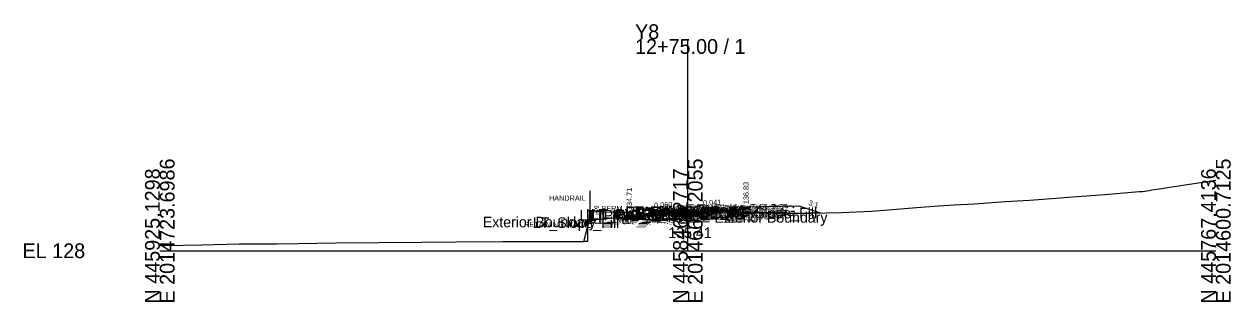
# Model space of a CAD drawing. Extents: x -26 to 1403, y -10 to 8043.
# Drawn here: x -25.7 to 202.8, y 5490.3 to 5543 of the extents above; entities that cross this region are included whole.
import ezdxf

# ---------------------------------------------------------------- set-up
doc = ezdxf.new("R2010")
doc.units = 0
for name, color, linetype in [('Default', 7, 'Continuous'), ('Exist CMT Pavement', 7, 'Continuous'), ('Exist Cross Section Cell', 7, 'Continuous'), ('Exist XS Center Line Elevation Label', 7, 'Continuous'), ('Exist XS Ground Line', 7, 'Continuous'), ('Prop CMT Conc Surface', 7, 'Continuous'), ('Prop CMT Concrete Structures', 7, 'Continuous'), ('Prop CMT Pvmt Course 1', 7, 'Continuous'), ('Prop CMT Pvmt Course 1 CG', 7, 'Continuous'), ('Prop CMT Pvmt Course 1 Wedge', 7, 'Continuous'), ('Prop CMT Pvmt Course 2', 7, 'Continuous'), ('Prop CMT Pvmt Course 2 Wedge', 7, 'Continuous'), ('Prop CMT Pvmt Course 3', 7, 'Continuous'), ('Prop CMT Pvmt Course 3 Wedge', 7, 'Continuous'), ('Prop CMT Pvmt Surface', 7, 'Continuous'), ('Prop CMT Pvmt Wedge Surface 1', 7, 'Continuous'), ('Prop CMT Pvmt Wedge Surface 2', 7, 'Continuous'), ('Prop CMT Pvmt Wedge Surface 3', 7, 'Continuous'), ('Prop CMT Slope Grass', 7, 'Continuous'), ('Prop CMT Subgrade Earthwork', 7, 'Continuous'), ('Prop XS Earthwork Shape', 7, 'Continuous'), ('Prop XS Hydro Elevations', 7, 'Continuous'), ('Prop XS Retaining Wall', 7, 'Continuous'), ('Prop XS SE Text', 7, 'Continuous'), ('Prop XS Side Slope Text', 7, 'Continuous'), ('Prop XS Vertical Lines', 7, 'Continuous'), ('Prop XS Wedging', 7, 'Continuous'), ('Scratch_Level_0', 7, 'Continuous')]:
    doc.layers.add(name, color=color, linetype=linetype)

msp = doc.modelspace()

# ---------------------------------------------------------------- linework, layer by layer
at = {"layer": 'Exist CMT Pavement'}
msp.add_lwpolyline([(91.92, 5506.74), (100.14, 5507.42), (107.98, 5507.57)], dxfattribs=at)
at = {"layer": 'Exist Cross Section Cell'}
for p, q in [((100, 5500), (100, 5540.12)), ((0, 5500), (100, 5500)), ((100, 5500), (200, 5500))]:
    msp.add_line(p, q, dxfattribs=at)
at = {"layer": 'Exist XS Ground Line'}
msp.add_lwpolyline([(0, 5501.01), (0.81, 5501.02), (7.95, 5501.11), (15.06, 5501.32), (20.63, 5501.3), (22.18, 5501.31), (26.19, 5501.38), (33.31, 5501.53), (49.55, 5501.63), (56.04, 5501.69), (64.94, 5501.74), (68.16, 5501.77), (75.26, 5501.75), (79.61, 5501.76), (80.32, 5501.76), (80.7, 5503.19), (81.37, 5505.83), (82.14, 5505.89), (85.97, 5506.23), (88.19, 5506.43), (89.76, 5506.56), (90.69, 5506.63), (100.14, 5507.42), (108.04, 5507.57), (108.43, 5507.54), (108.86, 5507.5), (109.95, 5507.38), (110.41, 5507.34), (112.61, 5507.23), (113.06, 5507.22), (113.53, 5507.21), (114.01, 5507.21), (114.64, 5507.21), (115.24, 5507.19), (116.01, 5507.18), (116.76, 5507.17), (117.48, 5507.16), (118.17, 5507.16), (118.81, 5507.15), (119.41, 5507.15), (120.44, 5507.09), (129.07, 5507.23), (134.77, 5507.51), (138.02, 5507.73), (143.32, 5508.18), (147.46, 5508.51), (150.45, 5508.69), (154.28, 5508.92), (160.14, 5509.31), (164.7, 5509.6), (170.55, 5510.02), (172.82, 5510.21), (178.95, 5510.69), (185.5, 5511.21), (186.08, 5511.25), (187.34, 5511.4), (187.89, 5511.52), (188.84, 5511.68), (200, 5513.37)], dxfattribs=at)
at = {"layer": 'Prop CMT Conc Surface'}
for points in [[(109.03, 5507.83), (111.03, 5507.83)], [(111.03, 5507.83), (111.03, 5508.33), (111.53, 5508.33)], [(88.91, 5506.71), (88.91, 5507.21), (88.41, 5507.21)], [(90.91, 5506.91), (88.91, 5506.71)]]:
    msp.add_lwpolyline(points, dxfattribs=at)
at = {"layer": 'Prop CMT Concrete Structures'}
for points in [[(109.03, 5507.83), (111.03, 5507.83), (111.03, 5508.33), (111.53, 5508.33)], [(111.53, 5508.33), (111.53, 5507.35), (109.03, 5507.24)], [(109.03, 5507.24), (109.03, 5507.83)], [(90.91, 5506.91), (88.91, 5506.71), (88.91, 5507.21), (88.41, 5507.21)], [(88.41, 5507.21), (88.41, 5506.18), (90.91, 5506.33)], [(90.91, 5506.33), (90.91, 5506.91)]]:
    msp.add_lwpolyline(points, dxfattribs=at)
at = {"layer": 'Prop CMT Pvmt Course 1'}
for points in [[(100, 5507.46), (109.03, 5507.83)], [(107.98, 5507.66), (100, 5507.33)], [(107.98, 5507.53), (107.98, 5507.66)], [(109.03, 5507.83), (109.03, 5507.58)], [(109.03, 5507.83), (109.03, 5507.58)], [(100, 5507.46), (90.91, 5506.91)], [(90.91, 5506.91), (90.91, 5506.66)], [(90.91, 5506.91), (90.91, 5506.66)], [(90.91, 5506.66), (91.92, 5506.72)], [(91.92, 5506.85), (100, 5507.33)], [(91.92, 5506.72), (91.92, 5506.85)], [(100, 5507.21), (100, 5507.46)], [(100, 5507.21), (100, 5507.46)], [(100, 5507.33), (100, 5507.21), (100, 5507.21)], [(100, 5507.33), (100, 5507.21), (100, 5507.21)], [(109.03, 5507.58), (107.98, 5507.53)]]:
    msp.add_lwpolyline(points, dxfattribs=at)
at = {"layer": 'Prop CMT Pvmt Course 1 CG'}
for points in [[(90.91, 5506.33), (87.91, 5506.15), (87.6, 5505.84)], [(87.6, 5505.84), (90.91, 5506.04)], [(90.91, 5506.04), (90.91, 5506.33)], [(109.03, 5507.24), (112.03, 5507.37), (112.31, 5507.09)], [(109.03, 5506.95), (109.03, 5507.24)], [(112.31, 5507.09), (109.03, 5506.95)]]:
    msp.add_lwpolyline(points, dxfattribs=at)
at = {"layer": 'Prop CMT Pvmt Course 1 Wedge'}
for points in [[(100, 5507.33), (107.98, 5507.66)], [(100, 5507.33), (91.92, 5506.85)]]:
    msp.add_lwpolyline(points, dxfattribs=at)
at = {"layer": 'Prop CMT Pvmt Course 2'}
for points in [[(91.92, 5506.72), (90.91, 5506.66)], [(90.91, 5506.66), (90.91, 5506.41)], [(90.91, 5506.66), (90.91, 5506.41)], [(90.91, 5506.41), (91.92, 5506.47)], [(91.92, 5506.47), (91.92, 5506.72)], [(107.98, 5507.53), (109.03, 5507.58)], [(107.98, 5507.28), (107.98, 5507.53)], [(109.03, 5507.33), (107.98, 5507.28)], [(109.03, 5507.58), (109.03, 5507.33)], [(109.03, 5507.58), (109.03, 5507.33)]]:
    msp.add_lwpolyline(points, dxfattribs=at)
at = {"layer": 'Prop CMT Pvmt Course 2 Wedge'}
for points in [[(100, 5507.21), (91.92, 5506.72)], [(100, 5507.21), (107.98, 5507.53)]]:
    msp.add_lwpolyline(points, dxfattribs=at)
at = {"layer": 'Prop CMT Pvmt Course 3'}
for points in [[(91.92, 5506.47), (90.91, 5506.41)], [(90.91, 5506.41), (90.91, 5506.04)], [(90.91, 5506.41), (90.91, 5506.04)], [(90.91, 5506.04), (91.92, 5506.1)], [(91.92, 5506.1), (91.92, 5506.47)], [(107.98, 5507.28), (109.03, 5507.33)], [(107.98, 5506.91), (107.98, 5507.28)], [(109.03, 5506.95), (107.98, 5506.91)], [(109.03, 5507.33), (109.03, 5506.95)], [(109.03, 5507.33), (109.03, 5506.95)]]:
    msp.add_lwpolyline(points, dxfattribs=at)
at = {"layer": 'Prop CMT Pvmt Course 3 Wedge'}
for points in [[(100, 5506.96), (91.92, 5506.47)], [(100, 5506.96), (107.98, 5507.28)]]:
    msp.add_lwpolyline(points, dxfattribs=at)
at = {"layer": 'Prop CMT Pvmt Surface'}
for points in [[(100, 5507.46), (109.03, 5507.83)], [(100, 5507.46), (90.91, 5506.91)]]:
    msp.add_lwpolyline(points, dxfattribs=at)
at = {"layer": 'Prop CMT Pvmt Wedge Surface 1'}
for points in [[(100, 5507.33), (107.98, 5507.66)], [(107.98, 5507.66), (107.98, 5507.53)], [(109.03, 5507.58), (109.03, 5507.83)], [(90.91, 5506.66), (90.91, 5506.91)], [(90.91, 5506.66), (90.91, 5506.91)], [(91.92, 5506.72), (90.91, 5506.66)], [(100, 5507.33), (91.92, 5506.85)], [(91.92, 5506.85), (91.92, 5506.72)], [(107.98, 5507.53), (109.03, 5507.58)]]:
    msp.add_lwpolyline(points, dxfattribs=at)
at = {"layer": 'Prop CMT Pvmt Wedge Surface 2'}
for points in [[(109.03, 5507.58), (109.03, 5507.83)], [(100, 5507.21), (90.91, 5506.66)], [(90.91, 5506.66), (90.91, 5506.91)], [(90.91, 5506.66), (90.91, 5506.91)], [(100, 5507.21), (109.03, 5507.58)]]:
    msp.add_lwpolyline(points, dxfattribs=at)
at = {"layer": 'Prop CMT Pvmt Wedge Surface 3'}
for points in [[(109.03, 5507.33), (109.03, 5507.83)], [(100, 5506.96), (90.91, 5506.41)], [(90.91, 5506.41), (90.91, 5506.91)], [(90.91, 5506.41), (90.91, 5506.91)], [(100, 5506.96), (109.03, 5507.33)]]:
    msp.add_lwpolyline(points, dxfattribs=at)
at = {"layer": 'Prop CMT Slope Grass'}
msp.add_line((121.03, 5508.52), (125.09, 5507.17), dxfattribs=at)
for points in [[(111.53, 5508.33), (121.03, 5508.52)], [(88.41, 5507.21), (81, 5507.36)]]:
    msp.add_lwpolyline(points, dxfattribs=at)
at = {"layer": 'Prop CMT Subgrade Earthwork'}
for p, q in [((81, 5507.36), (81, 5501.76)), ((91.92, 5506.1), (91.92, 5506.74)), ((107.98, 5506.91), (107.98, 5507.57)), ((81, 5501.76), (80.32, 5501.76))]:
    msp.add_line(p, q, dxfattribs=at)
for points in [[(109.03, 5506.95), (112.31, 5507.09), (113.59, 5508.37)], [(90.91, 5506.04), (87.6, 5505.84), (86.19, 5507.26)], [(91.92, 5506.1), (90.91, 5506.04)], [(107.98, 5506.91), (109.03, 5506.95)]]:
    msp.add_lwpolyline(points, dxfattribs=at)
at = {"layer": 'Prop XS Earthwork Shape'}
for points in [[(121.03, 5508.52), (125.09, 5507.17), (120.44, 5507.09), (119.41, 5507.15), (118.81, 5507.15), (118.17, 5507.16), (117.48, 5507.16), (116.76, 5507.17), (116.01, 5507.18), (115.24, 5507.19), (114.64, 5507.21), (114.01, 5507.21), (113.53, 5507.21), (113.06, 5507.22), (112.61, 5507.23), (112.45, 5507.24), (113.59, 5508.37)], [(121.03, 5508.52), (125.09, 5507.17), (120.44, 5507.09), (119.41, 5507.15), (118.81, 5507.15), (118.17, 5507.16), (117.48, 5507.16), (116.76, 5507.17), (116.01, 5507.18), (115.24, 5507.19), (114.64, 5507.21), (114.01, 5507.21), (113.53, 5507.21), (113.06, 5507.22), (112.61, 5507.23), (112.45, 5507.24), (113.59, 5508.37)], [(86.19, 5507.26), (81, 5507.36), (81, 5504.37), (81.37, 5505.83), (82.14, 5505.89), (85.97, 5506.23), (87.11, 5506.33)], [(86.19, 5507.26), (81, 5507.36), (81, 5504.37), (81.37, 5505.83), (82.14, 5505.89), (85.97, 5506.23), (87.11, 5506.33)], [(87.6, 5505.84), (87.11, 5506.33), (88.19, 5506.43), (88.41, 5506.45), (88.41, 5506.18), (90.91, 5506.33), (90.91, 5506.65), (91.92, 5506.74), (91.92, 5506.1), (90.91, 5506.04)], [(87.6, 5505.84), (87.11, 5506.33), (88.19, 5506.43), (88.41, 5506.45), (88.41, 5506.18), (90.91, 5506.33), (90.91, 5506.65), (91.92, 5506.74), (91.92, 5506.1), (90.91, 5506.04)], [(88.41, 5506.18), (90.91, 5506.33), (90.91, 5506.65), (90.69, 5506.63), (89.76, 5506.56), (88.41, 5506.45)], [(88.41, 5506.18), (90.91, 5506.33), (90.91, 5506.65), (90.69, 5506.63), (89.76, 5506.56), (88.41, 5506.45)], [(112.31, 5507.09), (112.45, 5507.24), (110.83, 5507.32), (109.03, 5507.24), (109.03, 5507.48), (108.86, 5507.5), (108.43, 5507.54), (108.04, 5507.57), (107.98, 5507.57), (107.98, 5506.91), (109.03, 5506.95)], [(112.31, 5507.09), (112.45, 5507.24), (110.83, 5507.32), (109.03, 5507.24), (109.03, 5507.48), (108.86, 5507.5), (108.43, 5507.54), (108.04, 5507.57), (107.98, 5507.57), (107.98, 5506.91), (109.03, 5506.95)], [(109.03, 5507.24), (109.03, 5507.48), (109.95, 5507.38), (110.41, 5507.34), (110.83, 5507.32)], [(109.03, 5507.24), (109.03, 5507.48), (109.95, 5507.38), (110.41, 5507.34), (110.83, 5507.32)], [(81, 5504.37), (81, 5501.76), (80.32, 5501.76), (80.7, 5503.19)], [(81, 5504.37), (81, 5501.76), (80.32, 5501.76), (80.7, 5503.19)]]:
    msp.add_lwpolyline(points, close=True, dxfattribs=at)
at = {"layer": 'Prop XS Retaining Wall'}
msp.add_line((81, 5507.91), (81, 5501.76), dxfattribs=at)
at = {"layer": 'Prop XS Vertical Lines'}
msp.add_line((81.5, 5507.35), (81.5, 5511.35), dxfattribs=at)
at = {"layer": 'Prop XS Wedging'}
for p, q in [((107.98, 5507.66), (104.08, 5507.5)), ((107.98, 5507.57), (107.98, 5507.66)), ((91.92, 5506.74), (96.6, 5507.13)), ((96.6, 5507.13), (91.92, 5506.85)), ((91.92, 5506.85), (91.92, 5506.74)), ((104.08, 5507.5), (107.98, 5507.57))]:
    msp.add_line(p, q, dxfattribs=at)

# ---------------------------------------------------------------- texts
at = {"layer": 'Default'}
msp.add_text('-', height=0.0001, dxfattribs=at).set_placement((0, 5500))
at = {"layer": 'Exist Cross Section Cell'}
for s, p in [('Y8', (90, 5540.12)), ('12+75.00 / 1', (90, 5537.32)), ('EL 128', (-26, 5498.6))]:
    msp.add_text(s, height=2.8, dxfattribs=at).set_placement(p)
for s, p in [('E 2014723.6986', (2.8, 5490)), ('E 2014662.2055', (102.8, 5490)), ('E 2014600.7125', (202.8, 5490)), ('N 445925.1298', (0, 5490)), ('N 445846.2717', (100, 5490)), ('N 445767.4136', (200, 5490))]:
    msp.add_text(s, height=2.8, rotation=90, dxfattribs=at).set_placement(p)
at = {"layer": 'Exist XS Center Line Elevation Label'}
msp.add_text('135.41', height=2, dxfattribs=at).set_placement((96.32, 5502.41))
at = {"layer": 'Prop XS Hydro Elevations'}
for s, p in [('136.83', (111.53, 5508.83)), ('134.71', (89.41, 5507.71))]:
    msp.add_text(s, height=1, rotation=90, dxfattribs=at).set_placement(p)
for s, p in [('HANDRAIL', (73.69, 5509.47)), ("8' BERM", (82.22, 5507.51)), ('RETAINING WALL', (68.98, 5504.48))]:
    msp.add_text(s, height=1, dxfattribs=at).set_placement(p)
at = {"layer": 'Prop XS SE Text'}
for s, rotation, p in [('0.060', 3.4336, (93.65, 5508.08)), ('0.041', 2.339, (102.91, 5508.58))]:
    msp.add_text(s, height=1, rotation=rotation, dxfattribs=at).set_placement(p)
at = {"layer": 'Prop XS Side Slope Text'}
msp.add_text('3:1', height=1, rotation=341.5651, dxfattribs=at).set_placement((122.73, 5508.69))
at = {"layer": 'Scratch_Level_0'}
for s, p in [('LT_PV_OEEOP_EG', (79.46, 5505.74)), ('LT_PV2_OEOT', (81.09, 5505.66)), ('LT_PV2_OEEOP', (81.22, 5505.72)), ('LT_PV1_OEOT', (81.65, 5505.91)), ('LT_PV1_OEEOP', (81.79, 5505.85)), ('RT_PV_IEEOP_EG', (88.14, 5506.41)), ('LT_PV_IEEOP_EG', (88.19, 5506.41)), ('RT_PV2_IEEOP', (89.91, 5506.21)), ('RT_PV3_IEEOP', (89.91, 5505.96)), ('LT_PV2_IEEOP', (89.95, 5506.21)), ('LT_PV3_IEEOP', (89.95, 5505.96)), ('RT_PV1_IEEOP', (90.47, 5506.33)), ('LT_PV1_IEEOP', (90.52, 5506.33)), ('PV2_PGL', (93.91, 5506.21)), ('PV1_PGL', (94.47, 5506.46)), ('RT_PV_OEEOP_EG', (95.47, 5506.57)), ('RT_Sub_OEEOP', (97.14, 5505.91)), ('RT_PV2_OEEOP', (97.24, 5506.53)), ('RT_PV3_OEEOP', (97.24, 5506.28)), ('RT_PV1_OEEOP', (97.8, 5506.66)), ('RT_Sub_OEOT', (99.06, 5505.95)), ('RT_PV2_OEOT', (99.15, 5506.58)), ('RT_PV3_OEOT', (99.15, 5506.33)), ('RT_PV1_OEOT', (99.72, 5506.83)), ('RT_Slope_Fill', (107.7, 5506.14)), ('Exterior Boundary', (61.17, 5504.44)), ('LT_Slope_Fill', (70.66, 5504.33)), ('LT_Sub_OEOT', (80.99, 5505.04)), ('LT_PV3_OEOT', (81.09, 5505.41)), ('LT_Sub_OEEOP', (81.13, 5505.1)), ('LT_PV3_OEEOP', (81.22, 5505.47)), ('Exterior Boundary', (105.03, 5505.32))]:
    msp.add_text(s, height=2, dxfattribs=at).set_placement(p)

doc.saveas('drawing.dxf')
